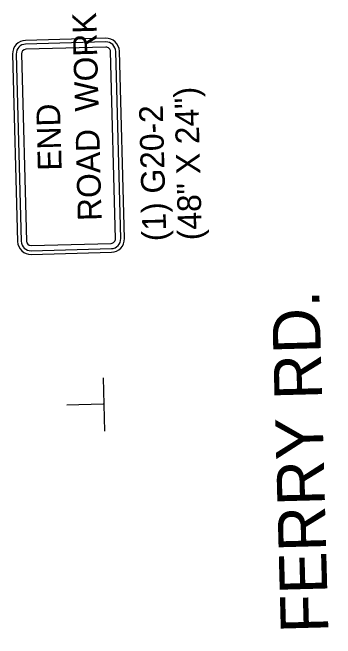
# Model space of a CAD drawing. Extents: x 1929653 to 1931621, y 596452 to 600944.
# Drawn here: x 1930001.1 to 1930123.4, y 598623.7 to 598860.5 of the extents above; entities that cross this region are included whole.
import ezdxf

# ---------------------------------------------------------------- set-up
doc = ezdxf.new("R2010")
doc.units = 0
for name, color, linetype in [('P_TC_Signs_Temporary', 7, 'Continuous'), ('R_Border', 7, 'Continuous'), ('R_Draft', 7, 'Continuous')]:
    doc.layers.add(name, color=color, linetype=linetype)

msp = doc.modelspace()

# ---------------------------------------------------------------- linework, layer by layer
at = {"layer": 'P_TC_Signs_Temporary'}
for p, q in [((1930036.37, 598850.79), (1930006, 598849.98)), ((1930036.4, 598849.39), (1930006.04, 598848.57)), ((1930036.46, 598847.42), (1930006.09, 598846.6)), ((1930001.08, 598844.78), (1930002.98, 598773.93)), ((1930002.48, 598844.82), (1930004.38, 598773.97)), ((1930004.45, 598844.87), (1930006.35, 598774.02)), ((1930040.09, 598774.93), (1930038.19, 598845.78)), ((1930042.06, 598774.98), (1930040.16, 598845.83)), ((1930043.46, 598775.02), (1930041.56, 598845.87)), ((1930008.09, 598772.38), (1930038.45, 598773.19)), ((1930008.14, 598770.41), (1930038.5, 598771.23)), ((1930008.18, 598769.01), (1930038.54, 598769.82))]:
    msp.add_line(p, q, dxfattribs=at)
for centre, radius, start, end in [((1930036.5, 598845.73), 5.06, 1.5377, 91.5377), ((1930006.14, 598844.92), 5.06, 91.5377, 181.5377), ((1930006.14, 598844.92), 3.66, 91.5377, 181.5377), ((1930036.5, 598845.73), 3.66, 1.5377, 91.5377), ((1930006.14, 598844.92), 1.69, 91.5377, 181.5377), ((1930036.5, 598845.73), 1.69, 1.5377, 91.5377), ((1930038.4, 598774.88), 3.66, 271.5377, 1.5377), ((1930038.4, 598774.88), 5.06, 271.5377, 1.5377), ((1930008.04, 598774.07), 5.06, 181.5377, 271.5377), ((1930008.04, 598774.07), 3.66, 181.5377, 271.5377), ((1930008.04, 598774.07), 1.69, 181.5377, 271.5377), ((1930038.4, 598774.88), 1.69, 271.5377, 1.5377)]:
    msp.add_arc(centre, radius, start, end, dxfattribs=at)
at = {"layer": 'R_Draft'}
for p, q in [((1930035.4, 598722.35), (1930035.94, 598702.16)), ((1930035.38, 598712.3), (1930021.6, 598711.93))]:
    msp.add_line(p, q, dxfattribs=at)

# ---------------------------------------------------------------- texts
at = {"layer": 'P_TC_Signs_Temporary'}
for s, p in [('ROAD  WORK', (1930034.84, 598781.79)), ('END', (1930019.7, 598800.78))]:
    msp.add_text(s, height=9, rotation=91.5377, dxfattribs=at).set_placement(p)
at = {"layer": 'R_Border'}
for s, height, p in [('(48" X 24")', 9, (1930072.84, 598774.47)), ('(1) G20-2', 9, (1930059.34, 598774.11)), ('BLACKS FERRY RD.', 18, (1930123.42, 598524.34))]:
    msp.add_text(s, height=height, rotation=91.5377, dxfattribs=at).set_placement(p)

doc.saveas('drawing.dxf')
